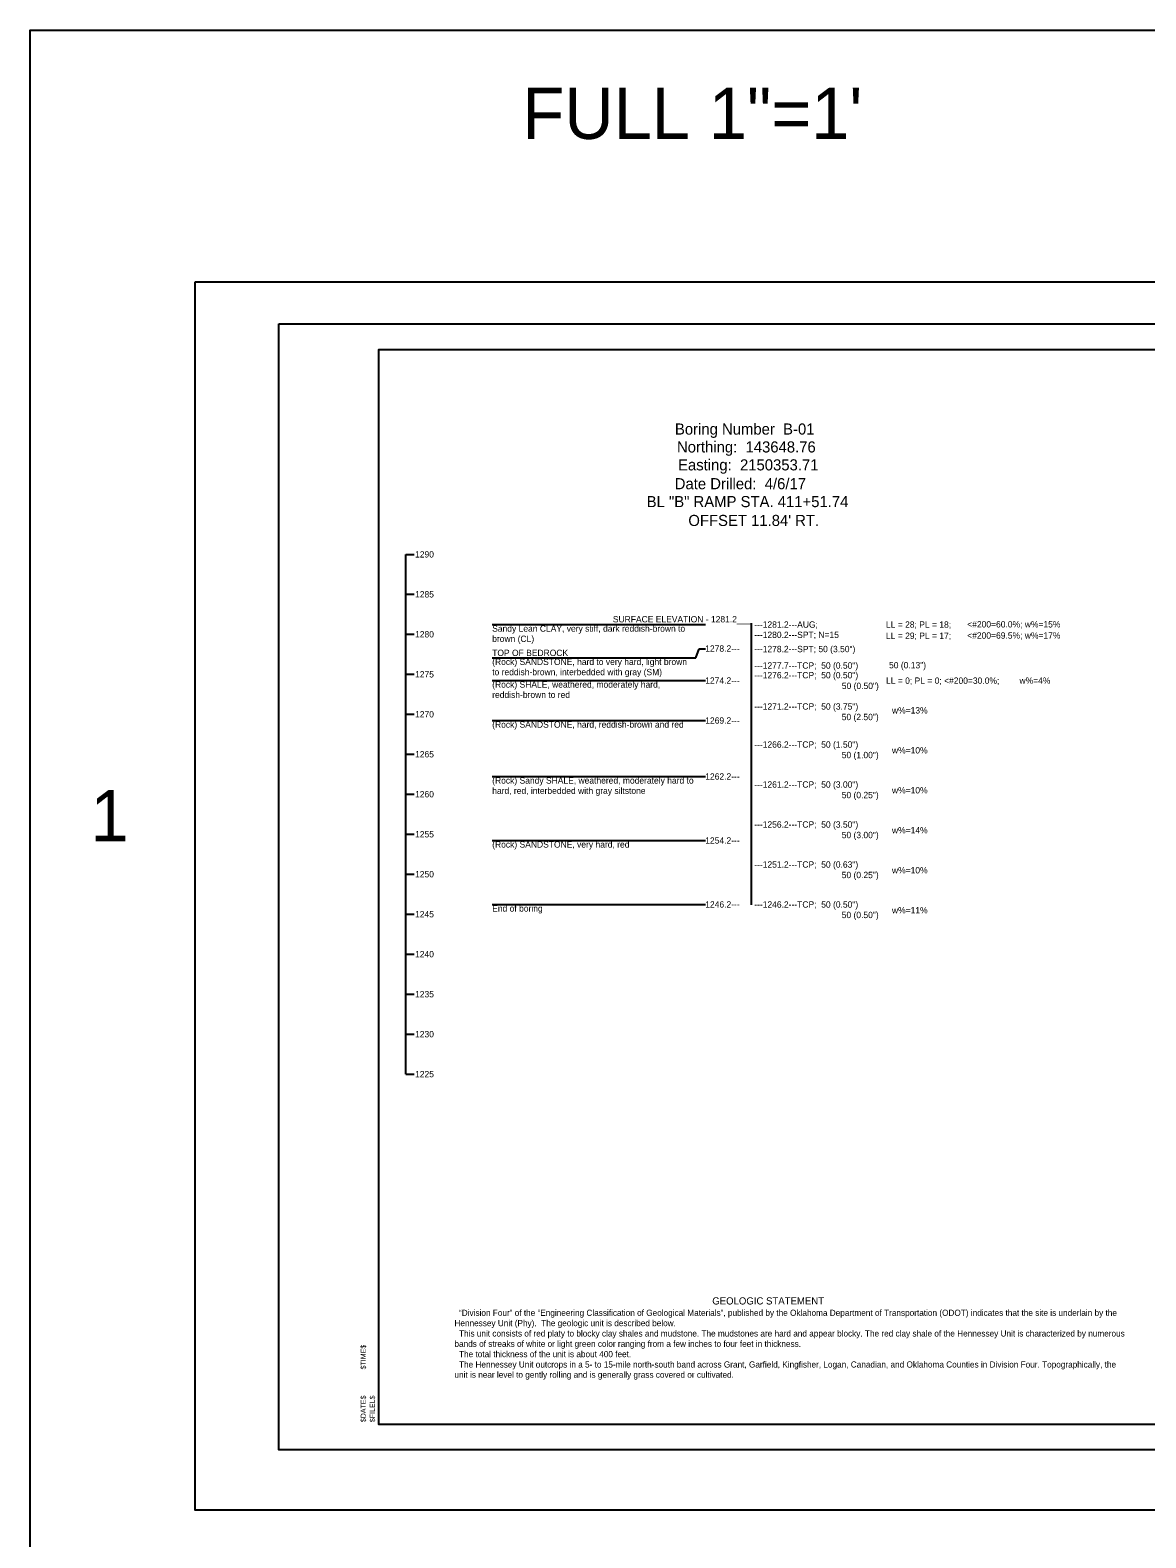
# Model space of a CAD drawing. Extents: x 2150162 to 2150245, y 143729 to 143865.
# Drawn here: x 2150161.57 to 2150183.36, y 143835.6 to 143865.06 of the extents above; entities that cross this region are included whole.
import ezdxf

# ---------------------------------------------------------------- set-up
doc = ezdxf.new("R2010")
doc.units = 0
for name, color, linetype in [('Default', 7, 'Continuous'), ('S', 7, 'Continuous'), ('SHT_Plot_Shape_Full', 7, 'Continuous'), ('SHT_Plot_Shape_Half', 7, 'Continuous'), ('SHT_Plot_Stamp', 7, 'Continuous'), ('SHT_Sheet_Border', 7, 'Continuous'), ('Text', 7, 'Continuous')]:
    doc.layers.add(name, color=color, linetype=linetype)

# ---------------------------------------------------------------- blocks, each defined once
blk = doc.blocks.new('Stamp_Plot_Stamp')
at = {"layer": 'SHT_Plot_Stamp'}
for s, p in [('$TIME$', (1.695, 1.572)), ('$DATE$', (1.695, 0.542)), ('$FILEL$', (1.873, 0.542))]:
    blk.add_text(s, height=0.1, rotation=90, dxfattribs=at).set_placement(p)

msp = doc.modelspace()

# ---------------------------------------------------------------- linework, layer by layer
at = {"layer": 'Default'}
for p, q in [((2150168.905, 143844.663), (2150168.905, 143854.819)), ((2150174.573, 143852.798), (2150174.639, 143852.975)), ((2150174.639, 143852.975), (2150174.761, 143852.975))]:
    msp.add_line(p, q, dxfattribs=at)
for points in [[(2150168.905, 143854.819), (2150169.071, 143854.819)], [(2150168.905, 143854.038), (2150169.071, 143854.038)], [(2150168.905, 143853.257), (2150169.071, 143853.257)], [(2150170.594, 143853.448), (2150174.761, 143853.448)], [(2150175.655, 143853.476), (2150175.655, 143847.974)], [(2150170.594, 143852.798), (2150174.573, 143852.798)], [(2150168.905, 143852.475), (2150169.071, 143852.475)], [(2150170.594, 143852.354), (2150174.761, 143852.354)], [(2150168.905, 143851.694), (2150169.071, 143851.694)], [(2150170.594, 143851.573), (2150174.761, 143851.573)], [(2150168.905, 143850.913), (2150169.071, 143850.913)], [(2150170.594, 143850.479), (2150174.761, 143850.479)], [(2150168.905, 143850.132), (2150169.071, 143850.132)], [(2150168.905, 143849.35), (2150169.071, 143849.35)], [(2150170.594, 143849.229), (2150174.761, 143849.229)], [(2150168.905, 143848.569), (2150169.071, 143848.569)], [(2150170.594, 143847.979), (2150174.761, 143847.979)], [(2150168.905, 143847.788), (2150169.071, 143847.788)], [(2150168.905, 143847.007), (2150169.071, 143847.007)], [(2150168.905, 143846.225), (2150169.071, 143846.225)], [(2150168.905, 143845.444), (2150169.071, 143845.444)], [(2150168.905, 143844.663), (2150169.071, 143844.663)]]:
    msp.add_lwpolyline(points, dxfattribs=at)
at = {"layer": 'S'}
msp.add_lwpolyline([(2150203.404, 143784.341), (2150161.568, 143784.341), (2150161.568, 143865.061), (2150203.404, 143865.061)], close=True, dxfattribs=at)
at = {"layer": 'SHT_Plot_Shape_Full'}
msp.add_lwpolyline([(2150164.792, 143860.145), (2150200.792, 143860.145), (2150200.792, 143836.145), (2150164.792, 143836.145)], close=True, dxfattribs=at)
at = {"layer": 'SHT_Plot_Shape_Half'}
msp.add_lwpolyline([(2150166.429, 143859.32), (2150200.429, 143859.32), (2150200.429, 143837.32), (2150166.429, 143837.32)], close=True, dxfattribs=at)
at = {"layer": 'SHT_Sheet_Border'}
msp.add_lwpolyline([(2150199.879, 143837.82), (2150168.379, 143837.82), (2150168.379, 143858.82), (2150199.879, 143858.82)], close=True, dxfattribs=at)

# ---------------------------------------------------------------- block references
at = {"layer": 'SHT_Plot_Stamp'}
msp.add_blockref('Stamp_Plot_Stamp', (2150166.429, 143837.32), dxfattribs=at)

# ---------------------------------------------------------------- texts
at = {"layer": 'Default'}
for s, height, p in [('Boring Number  B-01', 0.217, (2150174.164, 143857.159)), ('Northing:  143648.76', 0.217, (2150174.204, 143856.809)), ('Easting:  2150353.71', 0.217, (2150174.225, 143856.459)), ('Date Drilled:  4/6/17', 0.217, (2150174.16, 143856.091)), ('BL "B" RAMP STA. 411+51.74', 0.217, (2150173.612, 143855.741)), ("OFFSET 11.84' RT.", 0.217, (2150174.426, 143855.373)), ('1290', 0.124, (2150169.087, 143854.757)), ('1285', 0.124, (2150169.087, 143853.976)), ('SURFACE ELEVATION - 1281.2___', 0.124, (2150172.951, 143853.489)), ('1280', 0.124, (2150169.087, 143853.195)), ('Sandy Lean CLAY, very stiff, dark reddish-brown to', 0.124, (2150170.594, 143853.307)), ('---1281.2---AUG;', 0.124, (2150175.713, 143853.385)), ('---1280.2---SPT; N=15', 0.124, (2150175.713, 143853.185)), ('LL = 28; PL = 18;', 0.124, (2150178.287, 143853.385)), ('LL = 29; PL = 17;', 0.124, (2150178.287, 143853.167)), ('<#200=60.0%; w%=15%', 0.124, (2150179.874, 143853.39)), ('<#200=69.5%; w%=17%', 0.124, (2150179.874, 143853.172)), ('TOP OF BEDROCK', 0.124, (2150170.594, 143852.832)), ('brown (CL)', 0.124, (2150170.594, 143853.107)), ('1278.2---', 0.124, (2150174.756, 143852.917)), ('---1278.2---SPT; 50 (3.50")', 0.124, (2150175.713, 143852.907)), ('(Rock) SANDSTONE, hard to very hard, light brown', 0.124, (2150170.594, 143852.657)), ('---1277.7---TCP;  50 (0.50")', 0.124, (2150175.713, 143852.585)), ('50 (0.13")', 0.124, (2150178.347, 143852.591)), ('1275', 0.124, (2150169.087, 143852.413)), ('to reddish-brown, interbedded with gray (SM)', 0.124, (2150170.594, 143852.457)), ('1274.2---', 0.124, (2150174.756, 143852.292)), ('---1276.2---TCP;  50 (0.50")', 0.124, (2150175.713, 143852.396)), ('LL = 0; PL = 0; <#200=30.0%;', 0.124, (2150178.288, 143852.289)), ('w%=4%', 0.124, (2150180.895, 143852.29)), ('(Rock) SHALE, weathered, moderately hard,', 0.124, (2150170.594, 143852.214)), ('reddish-brown to red', 0.124, (2150170.594, 143852.014)), ('50 (0.50")', 0.124, (2150177.424, 143852.187)), ('---1271.2---TCP;  50 (3.75")', 0.124, (2150175.713, 143851.785)), ('w%=13%', 0.124, (2150178.404, 143851.709)), ('1270', 0.124, (2150169.087, 143851.632)), ('(Rock) SANDSTONE, hard, reddish-brown and red', 0.124, (2150170.594, 143851.432)), ('1269.2---', 0.124, (2150174.756, 143851.511)), ('50 (2.50")', 0.124, (2150177.422, 143851.579)), ('1265', 0.124, (2150169.087, 143850.851)), ('---1266.2---TCP;  50 (1.50")', 0.124, (2150175.713, 143851.041)), ('50 (1.00")', 0.124, (2150177.422, 143850.836)), ('w%=10%', 0.124, (2150178.404, 143850.928)), ('(Rock) Sandy SHALE, weathered, moderately hard to', 0.124, (2150170.594, 143850.339)), ('1262.2---', 0.124, (2150174.756, 143850.417)), ('---1261.2---TCP;  50 (3.00")', 0.124, (2150175.713, 143850.26)), ('1260', 0.124, (2150169.087, 143850.07)), ('hard, red, interbedded with gray siltstone', 0.124, (2150170.594, 143850.139)), ('50 (0.25")', 0.124, (2150177.422, 143850.054)), ('w%=10%', 0.124, (2150178.404, 143850.147)), ('---1256.2---TCP;  50 (3.50")', 0.124, (2150175.713, 143849.479)), ('w%=14%', 0.124, (2150178.404, 143849.366)), ('1255', 0.124, (2150169.087, 143849.288)), ('(Rock) SANDSTONE, very hard, red', 0.124, (2150170.594, 143849.089)), ('1254.2---', 0.124, (2150174.756, 143849.167)), ('50 (3.00")', 0.124, (2150177.422, 143849.273)), ('1250', 0.124, (2150169.087, 143848.507)), ('---1251.2---TCP;  50 (0.63")', 0.124, (2150175.713, 143848.697)), ('50 (0.25")', 0.124, (2150177.422, 143848.492)), ('w%=10%', 0.124, (2150178.404, 143848.584)), ('End of boring', 0.124, (2150170.594, 143847.839)), ('1246.2---', 0.124, (2150174.756, 143847.917)), ('---1246.2---TCP;  50 (0.50")', 0.124, (2150175.713, 143847.916)), ('1245', 0.124, (2150169.087, 143847.726)), ('50 (0.50")', 0.124, (2150177.422, 143847.711)), ('w%=11%', 0.124, (2150178.404, 143847.803)), ('1240', 0.124, (2150169.087, 143846.945)), ('1235', 0.124, (2150169.087, 143846.163)), ('1230', 0.124, (2150169.087, 143845.382)), ('1225', 0.124, (2150169.087, 143844.601))]:
    msp.add_text(s, height=height, dxfattribs=at).set_placement(p)
at = {"layer": 'S'}
for s, p in [('FULL 1"=1\'', (2150171.186, 143862.936)), ('1', (2150162.748, 143849.212))]:
    msp.add_text(s, height=1, dxfattribs=at).set_placement(p)
at = {"layer": 'Text'}
for s, height, p in [('GEOLOGIC STATEMENT', 0.14, (2150174.893, 143840.162)), ('  “Division Four” of the “Engineering Classification of Geological Materials”, published by the Oklahoma Department of Transportation (ODOT) indicates that the site is underlain by the ', 0.12, (2150169.857, 143839.94)), ('Hennessey Unit (Phy).  The geologic unit is described below. ', 0.12, (2150169.857, 143839.738)), ('bands of streaks of white or light green color ranging from a few inches to four feet in thickness. ', 0.12, (2150169.857, 143839.334)), ('  This unit consists of red platy to blocky clay shales and mudstone. The mudstones are hard and appear blocky. The red clay shale of the Hennessey Unit is characterized by numerous ', 0.12, (2150169.857, 143839.536)), ('  The total thickness of the unit is about 400 feet.', 0.12, (2150169.857, 143839.132)), ('unit is near level to gently rolling and is generally grass covered or cultivated.', 0.12, (2150169.857, 143838.73)), ('  The Hennessey Unit outcrops in a 5- to 15-mile north-south band across Grant, Garfield, Kingfisher, Logan, Canadian, and Oklahoma Counties in Division Four. Topographically, the ', 0.12, (2150169.857, 143838.93))]:
    msp.add_text(s, height=height, dxfattribs=at).set_placement(p)

doc.saveas('drawing.dxf')
